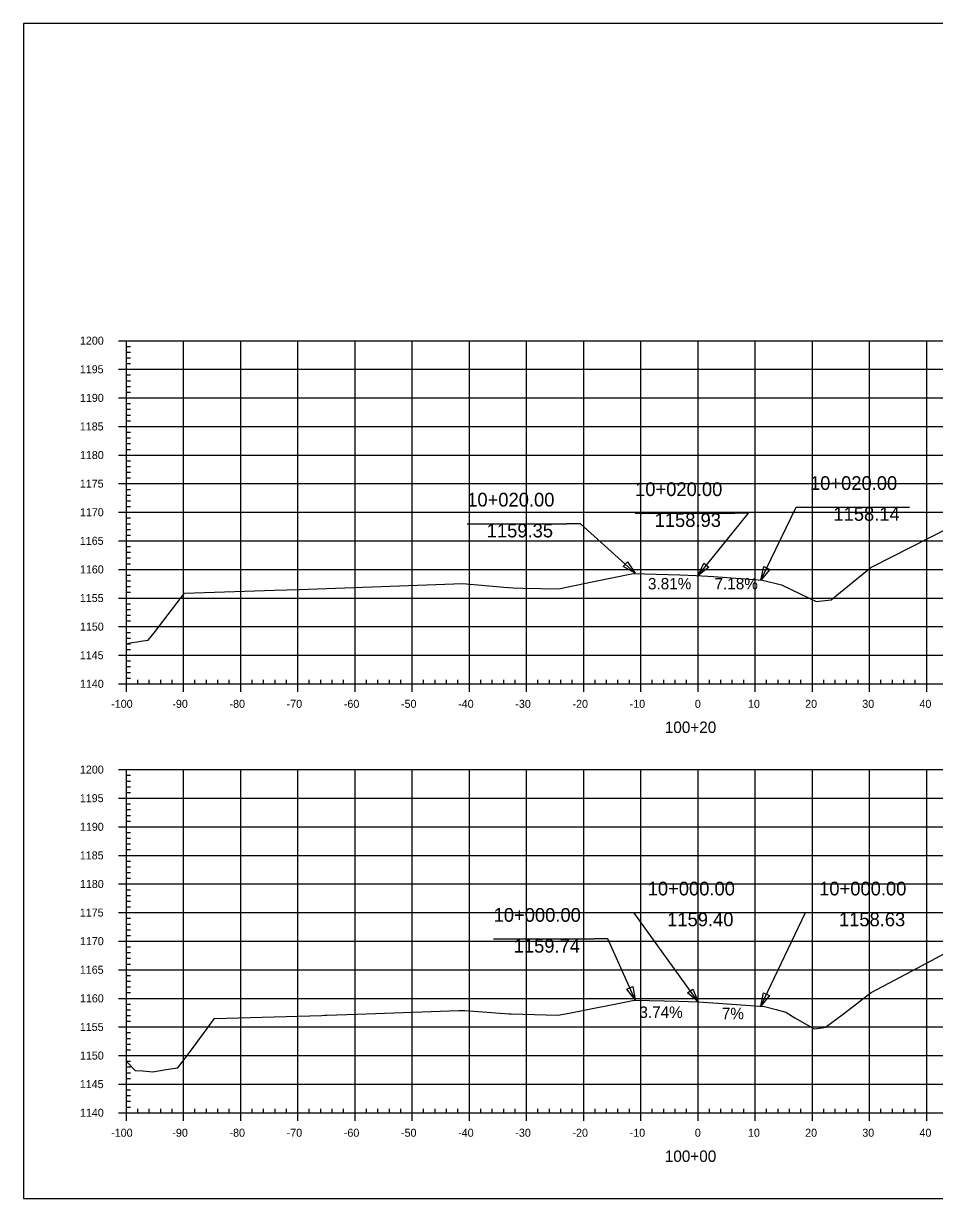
# Model space of a CAD drawing. Extents: x 688474 to 694748, y 765018 to 767373.
# Drawn here: x 689619.8 to 689779.2, y 765023.1 to 765228.6 of the extents above; entities that cross this region are included whole.
import ezdxf

# ---------------------------------------------------------------- set-up
doc = ezdxf.new("R2010")
doc.units = 0
for name, color, linetype in [('60', 7, 'Continuous'), ('Default', 7, 'Continuous'), ('R_Exist Surface', 7, 'Continuous'), ('R_Grid', 7, 'Continuous'), ('R_No Plot', 7, 'Continuous'), ('R_Xsect Slope', 7, 'Continuous')]:
    doc.layers.add(name, color=color, linetype=linetype)

msp = doc.modelspace()

# ---------------------------------------------------------------- linework, layer by layer
at = {"layer": '60'}
for p, q in [((689636.42, 765173.14), (689639.22, 765173.14)), ((689637.82, 765113.14), (689637.82, 765173.14)), ((689637.82, 765172.14), (689638.52, 765172.14)), ((689637.82, 765171.14), (689638.52, 765171.14)), ((689637.82, 765170.14), (689638.52, 765170.14)), ((689636.42, 765168.14), (689639.22, 765168.14)), ((689637.82, 765169.14), (689638.52, 765169.14)), ((689637.82, 765167.14), (689638.52, 765167.14)), ((689637.82, 765166.14), (689638.52, 765166.14)), ((689637.82, 765165.14), (689638.52, 765165.14)), ((689637.82, 765164.14), (689638.52, 765164.14)), ((689636.42, 765163.14), (689639.22, 765163.14)), ((689637.82, 765162.14), (689638.52, 765162.14)), ((689637.82, 765161.14), (689638.52, 765161.14)), ((689637.82, 765160.14), (689638.52, 765160.14)), ((689636.42, 765158.14), (689639.22, 765158.14)), ((689637.82, 765159.14), (689638.52, 765159.14)), ((689637.82, 765157.14), (689638.52, 765157.14)), ((689637.82, 765156.14), (689638.52, 765156.14)), ((689637.82, 765155.14), (689638.52, 765155.14)), ((689637.82, 765154.14), (689638.52, 765154.14)), ((689636.42, 765153.14), (689639.22, 765153.14)), ((689637.82, 765152.14), (689638.52, 765152.14)), ((689637.82, 765151.14), (689638.52, 765151.14)), ((689637.82, 765150.14), (689638.52, 765150.14)), ((689636.42, 765148.14), (689639.22, 765148.14)), ((689637.82, 765149.14), (689638.52, 765149.14)), ((689637.82, 765147.14), (689638.52, 765147.14)), ((689637.82, 765146.14), (689638.52, 765146.14)), ((689637.82, 765145.14), (689638.52, 765145.14)), ((689637.82, 765144.14), (689638.52, 765144.14)), ((689636.42, 765143.14), (689639.22, 765143.14)), ((689637.82, 765142.14), (689638.52, 765142.14)), ((689637.82, 765141.14), (689638.52, 765141.14)), ((689637.82, 765140.14), (689638.52, 765140.14)), ((689636.42, 765138.14), (689639.22, 765138.14)), ((689637.82, 765139.14), (689638.52, 765139.14)), ((689637.82, 765137.14), (689638.52, 765137.14)), ((689637.82, 765136.14), (689638.52, 765136.14)), ((689637.82, 765135.14), (689638.52, 765135.14)), ((689636.42, 765133.14), (689639.22, 765133.14)), ((689637.82, 765134.14), (689638.52, 765134.14)), ((689637.82, 765132.14), (689638.52, 765132.14)), ((689637.82, 765131.14), (689638.52, 765131.14)), ((689637.82, 765130.14), (689638.52, 765130.14)), ((689637.82, 765129.14), (689638.52, 765129.14)), ((689636.42, 765128.14), (689639.22, 765128.14)), ((689637.82, 765127.14), (689638.52, 765127.14)), ((689637.82, 765126.14), (689638.52, 765126.14)), ((689637.82, 765125.14), (689638.52, 765125.14)), ((689636.42, 765123.14), (689639.22, 765123.14)), ((689637.82, 765124.14), (689638.52, 765124.14)), ((689637.82, 765122.14), (689638.52, 765122.14)), ((689637.82, 765121.14), (689638.52, 765121.14)), ((689637.82, 765120.14), (689638.52, 765120.14)), ((689637.82, 765119.14), (689638.52, 765119.14)), ((689636.42, 765118.14), (689639.22, 765118.14)), ((689637.82, 765117.14), (689638.52, 765117.14)), ((689637.82, 765116.14), (689638.52, 765116.14)), ((689637.82, 765115.14), (689638.52, 765115.14)), ((689636.42, 765113.14), (689639.22, 765113.14)), ((689637.82, 765111.74), (689637.82, 765114.54)), ((689637.82, 765114.14), (689638.52, 765114.14)), ((689637.82, 765113.14), (689837.82, 765113.14)), ((689639.82, 765113.14), (689639.82, 765113.84)), ((689641.82, 765113.14), (689641.82, 765113.84)), ((689643.82, 765113.14), (689643.82, 765113.84)), ((689645.82, 765113.14), (689645.82, 765113.84)), ((689647.82, 765111.74), (689647.82, 765114.54)), ((689649.82, 765113.14), (689649.82, 765113.84)), ((689651.82, 765113.14), (689651.82, 765113.84)), ((689653.82, 765113.14), (689653.82, 765113.84)), ((689655.82, 765113.14), (689655.82, 765113.84)), ((689657.82, 765111.74), (689657.82, 765114.54)), ((689659.82, 765113.14), (689659.82, 765113.84)), ((689661.82, 765113.14), (689661.82, 765113.84)), ((689663.82, 765113.14), (689663.82, 765113.84)), ((689665.82, 765113.14), (689665.82, 765113.84)), ((689667.82, 765111.74), (689667.82, 765114.54)), ((689669.82, 765113.14), (689669.82, 765113.84)), ((689671.82, 765113.14), (689671.82, 765113.84)), ((689673.82, 765113.14), (689673.82, 765113.84)), ((689675.82, 765113.14), (689675.82, 765113.84)), ((689677.82, 765111.74), (689677.82, 765114.54)), ((689679.82, 765113.14), (689679.82, 765113.84)), ((689681.82, 765113.14), (689681.82, 765113.84)), ((689683.82, 765113.14), (689683.82, 765113.84)), ((689685.82, 765113.14), (689685.82, 765113.84)), ((689687.82, 765111.74), (689687.82, 765114.54)), ((689689.82, 765113.14), (689689.82, 765113.84)), ((689691.82, 765113.14), (689691.82, 765113.84)), ((689693.82, 765113.14), (689693.82, 765113.84)), ((689695.82, 765113.14), (689695.82, 765113.84)), ((689697.82, 765111.74), (689697.82, 765114.54)), ((689699.82, 765113.14), (689699.82, 765113.84)), ((689701.82, 765113.14), (689701.82, 765113.84)), ((689703.82, 765113.14), (689703.82, 765113.84)), ((689705.82, 765113.14), (689705.82, 765113.84)), ((689707.82, 765111.74), (689707.82, 765114.54)), ((689709.82, 765113.14), (689709.82, 765113.84)), ((689711.82, 765113.14), (689711.82, 765113.84)), ((689713.82, 765113.14), (689713.82, 765113.84)), ((689715.82, 765113.14), (689715.82, 765113.84)), ((689717.82, 765111.74), (689717.82, 765114.54)), ((689719.82, 765113.14), (689719.82, 765113.84)), ((689721.82, 765113.14), (689721.82, 765113.84)), ((689723.82, 765113.14), (689723.82, 765113.84)), ((689725.82, 765113.14), (689725.82, 765113.84)), ((689727.82, 765111.74), (689727.82, 765114.54)), ((689729.82, 765113.14), (689729.82, 765113.84)), ((689731.82, 765113.14), (689731.82, 765113.84)), ((689733.82, 765113.14), (689733.82, 765113.84)), ((689735.82, 765113.14), (689735.82, 765113.84)), ((689737.82, 765111.74), (689737.82, 765114.54)), ((689739.82, 765113.14), (689739.82, 765113.84)), ((689741.82, 765113.14), (689741.82, 765113.84)), ((689743.82, 765113.14), (689743.82, 765113.84)), ((689745.82, 765113.14), (689745.82, 765113.84)), ((689747.82, 765111.74), (689747.82, 765114.54)), ((689749.82, 765113.14), (689749.82, 765113.84)), ((689751.82, 765113.14), (689751.82, 765113.84)), ((689753.82, 765113.14), (689753.82, 765113.84)), ((689755.82, 765113.14), (689755.82, 765113.84)), ((689757.82, 765111.74), (689757.82, 765114.54)), ((689759.82, 765113.14), (689759.82, 765113.84)), ((689761.82, 765113.14), (689761.82, 765113.84)), ((689763.82, 765113.14), (689763.82, 765113.84)), ((689765.82, 765113.14), (689765.82, 765113.84)), ((689767.82, 765111.74), (689767.82, 765114.54)), ((689769.82, 765113.14), (689769.82, 765113.84)), ((689771.82, 765113.14), (689771.82, 765113.84)), ((689773.82, 765113.14), (689773.82, 765113.84)), ((689775.82, 765113.14), (689775.82, 765113.84)), ((689777.82, 765111.74), (689777.82, 765114.54)), ((689636.42, 765098.14), (689639.22, 765098.14)), ((689637.82, 765038.14), (689637.82, 765098.14)), ((689637.82, 765097.14), (689638.52, 765097.14)), ((689637.82, 765096.14), (689638.52, 765096.14)), ((689637.82, 765095.14), (689638.52, 765095.14)), ((689637.82, 765094.14), (689638.52, 765094.14)), ((689636.42, 765093.14), (689639.22, 765093.14)), ((689637.82, 765092.14), (689638.52, 765092.14)), ((689637.82, 765091.14), (689638.52, 765091.14)), ((689637.82, 765090.14), (689638.52, 765090.14)), ((689636.42, 765088.14), (689639.22, 765088.14)), ((689637.82, 765089.14), (689638.52, 765089.14)), ((689637.82, 765087.14), (689638.52, 765087.14)), ((689637.82, 765086.14), (689638.52, 765086.14)), ((689637.82, 765085.14), (689638.52, 765085.14)), ((689637.82, 765084.14), (689638.52, 765084.14)), ((689636.42, 765083.14), (689639.22, 765083.14)), ((689637.82, 765082.14), (689638.52, 765082.14)), ((689637.82, 765081.14), (689638.52, 765081.14)), ((689637.82, 765080.14), (689638.52, 765080.14)), ((689636.42, 765078.14), (689639.22, 765078.14)), ((689637.82, 765079.14), (689638.52, 765079.14)), ((689637.82, 765077.14), (689638.52, 765077.14)), ((689637.82, 765076.14), (689638.52, 765076.14)), ((689637.82, 765075.14), (689638.52, 765075.14)), ((689637.82, 765074.14), (689638.52, 765074.14)), ((689636.42, 765073.14), (689639.22, 765073.14)), ((689637.82, 765072.14), (689638.52, 765072.14)), ((689637.82, 765071.14), (689638.52, 765071.14)), ((689637.82, 765070.14), (689638.52, 765070.14)), ((689636.42, 765068.14), (689639.22, 765068.14)), ((689637.82, 765069.14), (689638.52, 765069.14)), ((689637.82, 765067.14), (689638.52, 765067.14)), ((689637.82, 765066.14), (689638.52, 765066.14)), ((689637.82, 765065.14), (689638.52, 765065.14)), ((689637.82, 765064.14), (689638.52, 765064.14)), ((689636.42, 765063.14), (689639.22, 765063.14)), ((689637.82, 765062.14), (689638.52, 765062.14)), ((689637.82, 765061.14), (689638.52, 765061.14)), ((689637.82, 765060.14), (689638.52, 765060.14)), ((689637.82, 765059.14), (689638.52, 765059.14)), ((689636.42, 765058.14), (689639.22, 765058.14)), ((689637.82, 765057.14), (689638.52, 765057.14)), ((689637.82, 765056.14), (689638.52, 765056.14)), ((689637.82, 765055.14), (689638.52, 765055.14)), ((689636.42, 765053.14), (689639.22, 765053.14)), ((689637.82, 765054.14), (689638.52, 765054.14)), ((689637.82, 765052.14), (689638.52, 765052.14)), ((689637.82, 765051.14), (689638.52, 765051.14)), ((689637.82, 765050.14), (689638.52, 765050.14)), ((689637.82, 765049.14), (689638.52, 765049.14)), ((689636.42, 765048.14), (689639.22, 765048.14)), ((689637.82, 765047.14), (689638.52, 765047.14)), ((689637.82, 765046.14), (689638.52, 765046.14)), ((689637.82, 765045.14), (689638.52, 765045.14)), ((689636.42, 765043.14), (689639.22, 765043.14)), ((689637.82, 765044.14), (689638.52, 765044.14)), ((689637.82, 765042.14), (689638.52, 765042.14)), ((689637.82, 765041.14), (689638.52, 765041.14)), ((689637.82, 765040.14), (689638.52, 765040.14)), ((689637.82, 765036.74), (689637.82, 765039.54)), ((689637.82, 765039.14), (689638.52, 765039.14)), ((689639.82, 765038.14), (689639.82, 765038.84)), ((689641.82, 765038.14), (689641.82, 765038.84)), ((689643.82, 765038.14), (689643.82, 765038.84)), ((689645.82, 765038.14), (689645.82, 765038.84)), ((689647.82, 765036.74), (689647.82, 765039.54)), ((689649.82, 765038.14), (689649.82, 765038.84)), ((689651.82, 765038.14), (689651.82, 765038.84)), ((689653.82, 765038.14), (689653.82, 765038.84)), ((689655.82, 765038.14), (689655.82, 765038.84)), ((689657.82, 765036.74), (689657.82, 765039.54)), ((689659.82, 765038.14), (689659.82, 765038.84)), ((689661.82, 765038.14), (689661.82, 765038.84)), ((689663.82, 765038.14), (689663.82, 765038.84)), ((689665.82, 765038.14), (689665.82, 765038.84)), ((689667.82, 765036.74), (689667.82, 765039.54)), ((689669.82, 765038.14), (689669.82, 765038.84)), ((689671.82, 765038.14), (689671.82, 765038.84)), ((689673.82, 765038.14), (689673.82, 765038.84)), ((689675.82, 765038.14), (689675.82, 765038.84)), ((689677.82, 765036.74), (689677.82, 765039.54)), ((689679.82, 765038.14), (689679.82, 765038.84)), ((689681.82, 765038.14), (689681.82, 765038.84)), ((689683.82, 765038.14), (689683.82, 765038.84)), ((689685.82, 765038.14), (689685.82, 765038.84)), ((689687.82, 765036.74), (689687.82, 765039.54)), ((689689.82, 765038.14), (689689.82, 765038.84)), ((689691.82, 765038.14), (689691.82, 765038.84)), ((689693.82, 765038.14), (689693.82, 765038.84)), ((689695.82, 765038.14), (689695.82, 765038.84)), ((689697.82, 765036.74), (689697.82, 765039.54)), ((689699.82, 765038.14), (689699.82, 765038.84)), ((689701.82, 765038.14), (689701.82, 765038.84)), ((689703.82, 765038.14), (689703.82, 765038.84)), ((689705.82, 765038.14), (689705.82, 765038.84)), ((689707.82, 765036.74), (689707.82, 765039.54)), ((689709.82, 765038.14), (689709.82, 765038.84)), ((689711.82, 765038.14), (689711.82, 765038.84)), ((689713.82, 765038.14), (689713.82, 765038.84)), ((689715.82, 765038.14), (689715.82, 765038.84)), ((689717.82, 765036.74), (689717.82, 765039.54)), ((689719.82, 765038.14), (689719.82, 765038.84)), ((689721.82, 765038.14), (689721.82, 765038.84)), ((689723.82, 765038.14), (689723.82, 765038.84)), ((689725.82, 765038.14), (689725.82, 765038.84)), ((689727.82, 765036.74), (689727.82, 765039.54)), ((689729.82, 765038.14), (689729.82, 765038.84)), ((689731.82, 765038.14), (689731.82, 765038.84)), ((689733.82, 765038.14), (689733.82, 765038.84)), ((689735.82, 765038.14), (689735.82, 765038.84)), ((689737.82, 765036.74), (689737.82, 765039.54)), ((689739.82, 765038.14), (689739.82, 765038.84)), ((689741.82, 765038.14), (689741.82, 765038.84)), ((689743.82, 765038.14), (689743.82, 765038.84)), ((689745.82, 765038.14), (689745.82, 765038.84)), ((689747.82, 765036.74), (689747.82, 765039.54)), ((689749.82, 765038.14), (689749.82, 765038.84)), ((689751.82, 765038.14), (689751.82, 765038.84)), ((689753.82, 765038.14), (689753.82, 765038.84)), ((689755.82, 765038.14), (689755.82, 765038.84)), ((689757.82, 765036.74), (689757.82, 765039.54)), ((689759.82, 765038.14), (689759.82, 765038.84)), ((689761.82, 765038.14), (689761.82, 765038.84)), ((689763.82, 765038.14), (689763.82, 765038.84)), ((689765.82, 765038.14), (689765.82, 765038.84)), ((689767.82, 765036.74), (689767.82, 765039.54)), ((689769.82, 765038.14), (689769.82, 765038.84)), ((689771.82, 765038.14), (689771.82, 765038.84)), ((689773.82, 765038.14), (689773.82, 765038.84)), ((689775.82, 765038.14), (689775.82, 765038.84)), ((689777.82, 765036.74), (689777.82, 765039.54)), ((689636.42, 765038.14), (689639.22, 765038.14)), ((689637.82, 765038.14), (689837.82, 765038.14))]:
    msp.add_line(p, q, dxfattribs=at)
at = {"layer": 'R_Exist Surface'}
for p, q in [((689757.4, 765144.04), (689774.82, 765144.04)), ((689726.81, 765142.97), (689744.23, 765142.97)), ((689697.44, 765141.14), (689714.86, 765141.14)), ((689729.01, 765073.14), (689746.62, 765073.14)), ((689759.01, 765073.14), (689776.62, 765073.14)), ((689702.06, 765068.53), (689719.67, 765068.53))]:
    msp.add_line(p, q, dxfattribs=at)
for points in [[(689748.82, 765131.28), (689755, 765144.04), (689757.4, 765144.04)], [(689737.82, 765132.07), (689746.63, 765142.97), (689744.23, 765142.97)], [(689637.82, 765120.18), (689640.69, 765120.63), (689641.61, 765120.76), (689642.65, 765122.05), (689645.89, 765126.24), (689648.01, 765128.98), (689663.7, 765129.51), (689668.04, 765129.65), (689691.93, 765130.51), (689696.67, 765130.68), (689703.85, 765130.04), (689705.47, 765129.92), (689707.18, 765129.87), (689713.4, 765129.75), (689719.28, 765130.95), (689726.47, 765132.42), (689734.62, 765132.17), (689737.52, 765132.09), (689740.51, 765131.88), (689749.09, 765131.26), (689752.4, 765130.43), (689752.56, 765130.38), (689757.25, 765128.12), (689758.46, 765127.53), (689760.08, 765127.71), (689761.12, 765127.83), (689763.38, 765129.67), (689768.1, 765133.51), (689768.38, 765133.66), (689781.67, 765140.44)], [(689726.82, 765132.5), (689717.26, 765141.14), (689714.86, 765141.14)], [(689737.82, 765057.54), (689726.61, 765073.14), (689729.01, 765073.14)], [(689748.82, 765056.77), (689756.61, 765073.14), (689759.01, 765073.14)], [(689726.82, 765057.88), (689722.07, 765068.53), (689719.67, 765068.53)], [(689637.82, 765047.07), (689639.34, 765045.55), (689640.72, 765045.44), (689642.45, 765045.29), (689644.79, 765045.67), (689646.84, 765045.99), (689649.41, 765049.39), (689653.23, 765054.63), (689671.98, 765055.16), (689672.56, 765055.18), (689672.9, 765055.19), (689678.11, 765055.38), (689696, 765056.01), (689696.73, 765056.04), (689697.02, 765056.02), (689704.78, 765055.45), (689705.13, 765055.44), (689713.31, 765055.19), (689715.25, 765055.57), (689726.7, 765057.85), (689734.46, 765057.64), (689737.82, 765057.54), (689741.29, 765057.29), (689749.44, 765056.73), (689751.5, 765056.2), (689753.21, 765055.75), (689754.75, 765054.72), (689758.16, 765052.79), (689759.54, 765052.98), (689760.12, 765053.09), (689763.27, 765055.42), (689768.12, 765059.17), (689776.29, 765063.47), (689781.8, 765066.47)]]:
    msp.add_lwpolyline(points, dxfattribs=at)
for points in [[(689726.82, 765132.5), (689724.7, 765133.63), (689725.48, 765134.49)], [(689737.82, 765132.07), (689738.83, 765134.25), (689739.73, 765133.51)], [(689748.82, 765131.28), (689749.31, 765133.63), (689750.36, 765133.12)], [(689726.82, 765057.88), (689725.34, 765059.77), (689726.4, 765060.24)], [(689737.82, 765057.54), (689735.99, 765059.09), (689736.93, 765059.77)], [(689748.82, 765056.77), (689749.29, 765059.12), (689750.34, 765058.62)]]:
    msp.add_lwpolyline(points, close=True, dxfattribs=at)
at = {"layer": 'R_Grid'}
for p, q in [((689637.82, 765173.14), (689837.82, 765173.14)), ((689637.82, 765113.14), (689637.82, 765173.14)), ((689647.82, 765113.14), (689647.82, 765173.14)), ((689657.82, 765113.14), (689657.82, 765173.14)), ((689667.82, 765113.14), (689667.82, 765173.14)), ((689677.82, 765113.14), (689677.82, 765173.14)), ((689687.82, 765113.14), (689687.82, 765173.14)), ((689697.82, 765113.14), (689697.82, 765173.14)), ((689707.82, 765113.14), (689707.82, 765173.14)), ((689717.82, 765113.14), (689717.82, 765173.14)), ((689727.82, 765113.14), (689727.82, 765173.14)), ((689737.82, 765113.14), (689737.82, 765173.14)), ((689747.82, 765113.14), (689747.82, 765173.14)), ((689757.82, 765113.14), (689757.82, 765173.14)), ((689767.82, 765113.14), (689767.82, 765173.14)), ((689777.82, 765113.14), (689777.82, 765173.14)), ((689637.82, 765168.14), (689837.82, 765168.14)), ((689637.82, 765163.14), (689837.82, 765163.14)), ((689637.82, 765158.14), (689837.82, 765158.14)), ((689637.82, 765153.14), (689837.82, 765153.14)), ((689637.82, 765148.14), (689837.82, 765148.14)), ((689637.82, 765143.14), (689837.82, 765143.14)), ((689637.82, 765138.14), (689837.82, 765138.14)), ((689637.82, 765133.14), (689837.82, 765133.14)), ((689637.82, 765128.14), (689837.82, 765128.14)), ((689637.82, 765123.14), (689837.82, 765123.14)), ((689637.82, 765118.14), (689837.82, 765118.14)), ((689637.82, 765113.14), (689837.82, 765113.14)), ((689637.82, 765098.14), (689837.82, 765098.14)), ((689637.82, 765038.14), (689637.82, 765098.14)), ((689647.82, 765038.14), (689647.82, 765098.14)), ((689657.82, 765038.14), (689657.82, 765098.14)), ((689667.82, 765038.14), (689667.82, 765098.14)), ((689677.82, 765038.14), (689677.82, 765098.14)), ((689687.82, 765038.14), (689687.82, 765098.14)), ((689697.82, 765038.14), (689697.82, 765098.14)), ((689707.82, 765038.14), (689707.82, 765098.14)), ((689717.82, 765038.14), (689717.82, 765098.14)), ((689727.82, 765038.14), (689727.82, 765098.14)), ((689737.82, 765038.14), (689737.82, 765098.14)), ((689747.82, 765038.14), (689747.82, 765098.14)), ((689757.82, 765038.14), (689757.82, 765098.14)), ((689767.82, 765038.14), (689767.82, 765098.14)), ((689777.82, 765038.14), (689777.82, 765098.14)), ((689637.82, 765093.14), (689837.82, 765093.14)), ((689637.82, 765088.14), (689837.82, 765088.14)), ((689637.82, 765083.14), (689837.82, 765083.14)), ((689637.82, 765078.14), (689837.82, 765078.14)), ((689637.82, 765073.14), (689837.82, 765073.14)), ((689637.82, 765068.14), (689837.82, 765068.14)), ((689637.82, 765063.14), (689837.82, 765063.14)), ((689637.82, 765058.14), (689837.82, 765058.14)), ((689637.82, 765053.14), (689837.82, 765053.14)), ((689637.82, 765048.14), (689837.82, 765048.14)), ((689637.82, 765043.14), (689837.82, 765043.14)), ((689637.82, 765038.14), (689837.82, 765038.14))]:
    msp.add_line(p, q, dxfattribs=at)
at = {"layer": 'R_No Plot'}
msp.add_lwpolyline([(689619.82, 765023.14), (689936, 765023.14), (689936, 765228.6), (689619.82, 765228.6)], close=True, dxfattribs=at)

# ---------------------------------------------------------------- texts
at = {"layer": '60'}
for s, height, p in [('1200', 1.4, (689629.69, 765172.44)), ('1195', 1.4, (689629.67, 765167.44)), ('1190', 1.4, (689629.69, 765162.44)), ('1185', 1.4, (689629.67, 765157.44)), ('1180', 1.4, (689629.69, 765152.44)), ('1175', 1.4, (689629.67, 765147.44)), ('1170', 1.4, (689629.69, 765142.44)), ('1165', 1.4, (689629.67, 765137.44)), ('1160', 1.4, (689629.69, 765132.44)), ('1155', 1.4, (689629.67, 765127.44)), ('1150', 1.4, (689629.69, 765122.44)), ('1145', 1.4, (689629.67, 765117.44)), ('1140', 1.4, (689629.69, 765112.44)), ('-100', 1.4, (689635.16, 765108.94)), ('-90', 1.4, (689645.86, 765108.94)), ('-80', 1.4, (689655.86, 765108.94)), ('-70', 1.4, (689665.86, 765108.94)), ('-60', 1.4, (689675.86, 765108.94)), ('-50', 1.4, (689685.86, 765108.94)), ('-40', 1.4, (689695.86, 765108.94)), ('-30', 1.4, (689705.86, 765108.94)), ('-20', 1.4, (689715.86, 765108.94)), ('-10', 1.4, (689725.86, 765108.94)), ('0', 1.4, (689737.26, 765108.94)), ('10', 1.4, (689746.56, 765108.94)), ('20', 1.4, (689756.56, 765108.94)), ('30', 1.4, (689766.56, 765108.94)), ('40', 1.4, (689776.56, 765108.94)), ('100+20', 2, (689732.01, 765104.54)), ('1200', 1.4, (689629.69, 765097.44)), ('1195', 1.4, (689629.67, 765092.44)), ('1190', 1.4, (689629.69, 765087.44)), ('1185', 1.4, (689629.67, 765082.44)), ('1180', 1.4, (689629.69, 765077.44)), ('1175', 1.4, (689629.67, 765072.44)), ('1170', 1.4, (689629.69, 765067.44)), ('1165', 1.4, (689629.67, 765062.44)), ('1160', 1.4, (689629.69, 765057.44)), ('1155', 1.4, (689629.67, 765052.44)), ('1150', 1.4, (689629.69, 765047.44)), ('1145', 1.4, (689629.67, 765042.44)), ('1140', 1.4, (689629.69, 765037.44)), ('-100', 1.4, (689635.16, 765033.94)), ('-90', 1.4, (689645.86, 765033.94)), ('-80', 1.4, (689655.86, 765033.94)), ('-70', 1.4, (689665.86, 765033.94)), ('-60', 1.4, (689675.86, 765033.94)), ('-50', 1.4, (689685.86, 765033.94)), ('-40', 1.4, (689695.86, 765033.94)), ('-30', 1.4, (689705.86, 765033.94)), ('-20', 1.4, (689715.86, 765033.94)), ('-10', 1.4, (689725.86, 765033.94)), ('0', 1.4, (689737.26, 765033.94)), ('10', 1.4, (689746.56, 765033.94)), ('20', 1.4, (689756.56, 765033.94)), ('30', 1.4, (689766.56, 765033.94)), ('40', 1.4, (689776.56, 765033.94)), ('100+00', 2, (689732.01, 765029.54))]:
    msp.add_text(s, height=height, dxfattribs=at).set_placement(p)
at = {"layer": 'Default'}
for s, p in [('3.81%', (689729.06, 765129.65)), ('7.18%', (689740.71, 765129.65)), ('3.74%', (689727.56, 765054.72)), ('7%', (689741.99, 765054.49))]:
    msp.add_text(s, height=2, dxfattribs=at).set_placement(p)
at = {"layer": 'R_Xsect Slope'}
for s, p in [('10+020.00', (689726.81, 765145.97)), ('10+020.00', (689757.4, 765147.04)), ('10+020.00', (689697.44, 765144.14)), ('1158.14', (689761.5, 765141.64)), ('1158.93', (689730.23, 765140.57)), ('1159.35', (689700.85, 765138.74)), ('10+000.00', (689729.01, 765076.14)), ('10+000.00', (689759.01, 765076.14)), ('10+000.00', (689702.06, 765071.53)), ('1159.40', (689732.42, 765070.74)), ('1158.63', (689762.47, 765070.74)), ('1159.74', (689705.57, 765066.13))]:
    msp.add_text(s, height=2.4, dxfattribs=at).set_placement(p)

doc.saveas('drawing.dxf')
